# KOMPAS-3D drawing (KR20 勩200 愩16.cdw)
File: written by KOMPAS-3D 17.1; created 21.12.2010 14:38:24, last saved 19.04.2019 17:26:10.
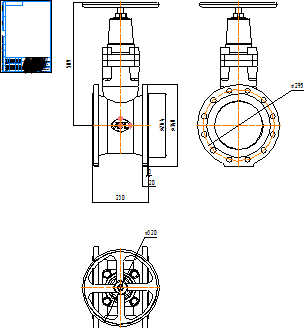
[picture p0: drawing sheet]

Title block, sheet 1: name: KR20 Ду200 Ру16; material: Внимание! Данный продукт является объектом авторского права ООО «Торговый Дом АДЛ». / Запрещается изменение, копирование, распространение / (в том числе путем копирования на другие сайты и ресурсы в Интернете) / или любое иное использование информации и объектов без предварительного / согласия правообладателя (ООО «Торговый Дом АДЛ»).; scale: 1:1; sheets: 1; organisation: ООО "Торговый дом АДЛ"; sheet format: A4; stored path: \\adlc.lan\data\АДЛ_ПКД\3D-модели\ADL production\Клиновые задвижки серии KR ГРАНАР\Клиновые задвижки KR20\KOMPAS 2D\KR20 Ду200 Ру16.cdw

Views: Спереди 1, Проекционный вид 2, Проекционный вид 3
Dimensions and other numbers on the sheet: 3; 230; 20; 264; 340; 509; 295; 320; 1:1; 1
